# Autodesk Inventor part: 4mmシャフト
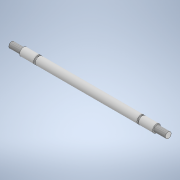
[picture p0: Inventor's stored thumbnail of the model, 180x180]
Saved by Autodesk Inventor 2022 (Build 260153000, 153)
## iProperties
Created: 2024-10
Part Number: 4mmシャフト
Material: 一般
Document SubType Name: Modeling
Designer: jsat7
Density: 1 g/cm^3
Appearance: 既定
Author: jsat7
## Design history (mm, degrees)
sketch "スケッチ1"
  geometry: L1 (0, 0)-(-40, 0); L2 (-40, 0)-(-40, -1.5); L3 (-40, -1.5)-(-34, -1.5); L4 (-34, -1.5)-(-34, -2); L5 (-34, -2)-(-26.8, -2); L6 (-26.8, -2)-(-26.8, -1.5); L7 (-26.8, -1.5)-(-26, -1.5); L8 (-26, -1.5)-(-26, -2); L9 (-26, -2)-(0, -2); L10 (0, -2)-(0, 0); L11 (-13, -26.74)-(-26.4, -26.74); L12 (-26.4, -26.74)-(-26.4, -24.724); L13 (-26.4, -24.724)-(-13, -24.724); L14 (-13, -24.724)-(-13, -26.74); C1 r 1.009 at (-29, 0)
  constraints: 28 end point, 8 perpendicular, 5 point on line, 2 horizontal, 2 parallel, 1 centre point
  dimensions: "d0" = 40 distance of L1.end L1.start; "d1" = 6 distance of L2.end L3.end; "d2" = 0.8 distance between parallel lines of L6 L8; "d3" = 2 distance between parallel lines of L1 L9; "d4" = 1.5 distance between parallel lines of L1 L3; "d5" = 26 distance between parallel lines of L10 L8; "d6" = 29 distance of L1.start C1.centre; "d7" = 2.01871 diameter of C1
revolve "回転1" stored, may be unused: angle "d8" = 90 deg
mirror "ミラー1"
feature "ねじ1" dims "d15" = 6, "d16" = 0
feature "ねじ2" dims "d17" = 6, "d18" = 0
node "ソリッド1"
